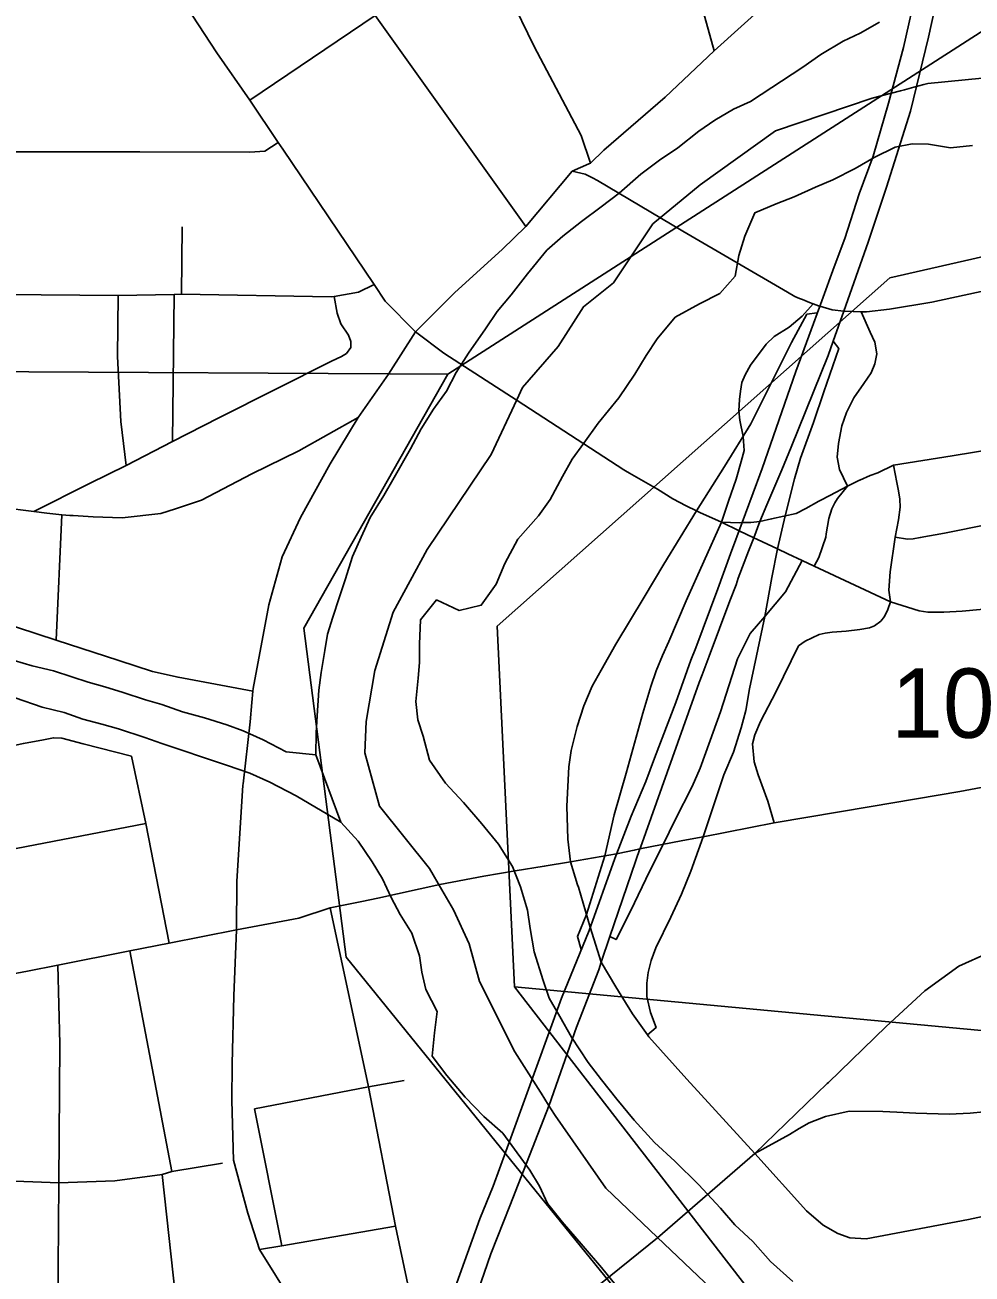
# Model space of a CAD drawing. Extents: x 0 to 34, y 0 to 22.
# Drawn here: x 5.363 to 5.934, y 17.938 to 18.692 of the extents above; entities that cross this region are included whole.
import ezdxf

# ---------------------------------------------------------------- set-up
doc = ezdxf.new("R2010")
doc.units = 0
for name, color, linetype in [('GM_X_City_Street', 7, 'Continuous'), ('GM_X_County_Road', 7, 'Continuous'), ('GM_X_Interchange_Ramps', 7, 'Continuous'), ('GM_X_Interstate_Route', 7, 'Continuous'), ('GM_X_Major_River', 7, 'Continuous'), ('GM_X_Minor_River', 7, 'Continuous'), ('GM_X_Section', 7, 'Continuous'), ('GM_X_Section_Text', 7, 'Continuous'), ('GM_X_State_Route', 7, 'Continuous'), ('GM_X_Township_Road', 7, 'Continuous')]:
    doc.layers.add(name, color=color, linetype=linetype)

msp = doc.modelspace()

# ---------------------------------------------------------------- linework, layer by layer
at = {"layer": 'GM_X_City_Street'}
for p, q in [((5.45717, 18.52964), (5.45757, 18.5704)), ((5.45169, 18.44072), (5.45272, 18.52956)), ((5.38163, 18.32096), (5.38501, 18.39665)), ((5.81473, 18.2106), (5.87317, 18.22049)), ((5.45134, 18.00021), (5.42602, 18.13345)), ((5.84669, 18.05335), (5.80309, 18.01104)), ((5.50112, 18.03802), (5.51773, 17.95544))]:
    msp.add_line(p, q, dxfattribs=at)
for points in [[(5.70382, 18.60876), (5.69817, 18.62546), (5.66986, 18.67924), (5.65476, 18.71038), (5.63867, 18.73899), (5.63778, 18.74057), (5.61042, 18.78398), (5.60565, 18.80325), (5.60403, 18.81271), (5.60004, 18.8227), (5.59103, 18.837), (5.5419, 18.90759), (5.49154, 18.98001), (5.48648, 18.98364), (5.48438, 19.10253), (5.48377, 19.19475), (5.48309, 19.26879), (5.48234, 19.35068), (5.47955, 19.41375), (5.47867, 19.47262), (5.47546, 19.62349)], [(5.41688, 18.92935), (5.466, 18.85737), (5.51512, 18.78539), (5.57404, 18.69794), (5.66478, 18.57054)], [(5.77846, 18.6766), (5.7719, 18.70057), (5.76891, 18.70952), (5.76443, 18.71698), (5.74653, 18.73116), (5.73459, 18.7431), (5.71893, 18.76025), (5.70102, 18.78711), (5.70231, 18.79249)], [(5.70282, 18.60832), (5.70382, 18.60876), (5.71196, 18.6166), (5.74884, 18.64863), (5.77846, 18.6766), (5.81113, 18.70604), (5.83996, 18.73212), (5.85236, 18.74295), (5.85686, 18.75026), (5.86172, 18.76)], [(5.49831, 18.64688), (5.57404, 18.69794), (5.61303, 18.72361), (5.63867, 18.73899)], [(5.01547, 18.61649), (5.06675, 18.61696), (5.11297, 18.61713), (5.18971, 18.61586), (5.20858, 18.61649), (5.2677, 18.61649), (5.27696, 18.61728), (5.34972, 18.61568), (5.43209, 18.61568), (5.49831, 18.61544), (5.50742, 18.616), (5.5155, 18.62119)], [(5.59837, 18.50708), (5.62194, 18.53082), (5.65069, 18.5566), (5.66478, 18.57054), (5.69283, 18.60395), (5.70282, 18.60832)], [(5.82279, 18.53086), (5.75954, 18.5677), (5.70806, 18.59831), (5.70506, 18.6), (5.70072, 18.60212), (5.69283, 18.60395)], [(6.01624, 18.5487), (5.9831, 18.54081), (5.90976, 18.52495), (5.88421, 18.52061), (5.8703, 18.51903), (5.86713, 18.51913), (5.85752, 18.51944), (5.85672, 18.51953), (5.84971, 18.52031), (5.84219, 18.52249), (5.84136, 18.52272), (5.83827, 18.52389), (5.83607, 18.52477), (5.83177, 18.52648)], [(5.06817, 18.52776), (5.11314, 18.52882), (5.18985, 18.52823), (5.20689, 18.5281), (5.26841, 18.52874), (5.34943, 18.52957), (5.41903, 18.529), (5.45272, 18.52956), (5.45717, 18.52964), (5.54743, 18.52805), (5.54926, 18.52837), (5.56395, 18.53091), (5.57328, 18.53553)], [(5.42374, 18.42642), (5.42059, 18.45299), (5.41854, 18.49211), (5.41903, 18.529)], [(5.83177, 18.52648), (5.83005, 18.52717), (5.82712, 18.52833), (5.82279, 18.53086)], [(5.36812, 18.39852), (5.4017, 18.41556), (5.42374, 18.42642), (5.45169, 18.44072), (5.47965, 18.45503), (5.54773, 18.48923), (5.55365, 18.49219), (5.55661, 18.49383), (5.55924, 18.49746), (5.55924, 18.50107), (5.55792, 18.50502), (5.55332, 18.51193), (5.55102, 18.51817), (5.54926, 18.52837)], [(5.83827, 18.52389), (5.83154, 18.51637), (5.82365, 18.50979), (5.8147, 18.50414), (5.80984, 18.49954), (5.80037, 18.48691), (5.79721, 18.48112), (5.79524, 18.47652), (5.79432, 18.47126), (5.79379, 18.46613), (5.7934, 18.45929), (5.79405, 18.45363), (5.79592, 18.44383), (5.79655, 18.43548), (5.79484, 18.42878), (5.79169, 18.41812), (5.78722, 18.40474), (5.78291, 18.39218)], [(5.83886, 18.36564), (5.84155, 18.37078), (5.84575, 18.38309), (5.84611, 18.38516), (5.84767, 18.39435), (5.84947, 18.40009), (5.85013, 18.40145), (5.85126, 18.40377), (5.85288, 18.40642), (5.85899, 18.41392), (5.85417, 18.42401), (5.85265, 18.43127), (5.85357, 18.43969), (5.85554, 18.45034), (5.8583, 18.45837), (5.86277, 18.46718), (5.86882, 18.47573), (5.87316, 18.4823), (5.8754, 18.48769), (5.87658, 18.49374), (5.8754, 18.50072), (5.87264, 18.50677), (5.86713, 18.51913)], [(5.56373, 18.45529), (5.58212, 18.48139), (5.59837, 18.50708)], [(5.59837, 18.50708), (5.61532, 18.49423), (5.65969, 18.46547), (5.72395, 18.42382), (5.72496, 18.4231), (5.7275, 18.42166)], [(5.49961, 18.28333), (5.50018, 18.2901), (5.50032, 18.29175), (5.50983, 18.34234), (5.51786, 18.37131), (5.52884, 18.39502), (5.54679, 18.42735), (5.56373, 18.45529)], [(5.50907, 18.42592), (5.52797, 18.43523), (5.56373, 18.45529)], [(5.9221, 18.43227), (5.94777, 18.43648), (6.03589, 18.45599)], [(5.76987, 18.39794), (5.78291, 18.39218), (5.79373, 18.39182), (5.79529, 18.39184), (5.80053, 18.39192), (5.80606, 18.39246), (5.81309, 18.39405), (5.82791, 18.39741), (5.83383, 18.40037), (5.84172, 18.40481), (5.84235, 18.40514), (5.84833, 18.40831), (5.85899, 18.41392), (5.86621, 18.41747), (5.86637, 18.41753), (5.8726, 18.42026), (5.87721, 18.42184), (5.8867, 18.42646), (5.9221, 18.43227)], [(5.45355, 18.40019), (5.46931, 18.40536), (5.49962, 18.42127), (5.50907, 18.42592)], [(5.8848, 18.34406), (5.88392, 18.35111), (5.88471, 18.36211), (5.88765, 18.383), (5.88968, 18.39358), (5.89076, 18.40128), (5.89056, 18.40611), (5.88978, 18.41104), (5.88869, 18.41617), (5.8867, 18.42646)], [(4.82442, 18.39738), (4.88136, 18.40769), (4.91451, 18.41344), (4.93894, 18.4177), (4.96998, 18.42088), (4.97641, 18.42021), (5.00584, 18.41716), (5.0685, 18.40656), (5.10561, 18.40028), (5.12583, 18.39754), (5.14022, 18.39445), (5.18923, 18.3828), (5.2629, 18.35744), (5.3225, 18.34033), (5.38163, 18.32096), (5.41936, 18.30873), (5.43975, 18.3021), (5.45504, 18.29853), (5.50018, 18.2901)], [(5.7275, 18.42166), (5.74437, 18.4121), (5.75358, 18.40622), (5.76157, 18.40198), (5.76785, 18.39892), (5.76987, 18.39794)], [(5.29075, 18.41333), (5.30709, 18.40994), (5.3326, 18.40449), (5.34896, 18.401), (5.36812, 18.39852), (5.37599, 18.3975), (5.38501, 18.39665), (5.38973, 18.3962), (5.39175, 18.39607)], [(5.88765, 18.383), (5.8951, 18.38185), (5.89846, 18.38204), (5.9028, 18.38283), (5.9174, 18.3855), (6.00035, 18.40226)], [(5.39175, 18.39607), (5.4039, 18.39533), (5.42134, 18.39467), (5.44468, 18.39729), (5.45355, 18.40019)], [(5.78291, 18.39218), (5.7935, 18.38694), (5.80236, 18.38278), (5.80472, 18.38168), (5.81678, 18.37601), (5.82299, 18.37309), (5.83158, 18.36906), (5.83886, 18.36564), (5.8848, 18.34406), (5.90225, 18.33863), (5.90748, 18.33784), (5.91705, 18.33784), (5.928, 18.33843), (5.93905, 18.33952), (6.00716, 18.35064), (6.05364, 18.35922), (6.05869, 18.36005)], [(5.81473, 18.2106), (5.81087, 18.22386), (5.80495, 18.23964), (5.80258, 18.2474), (5.80153, 18.25832), (5.80298, 18.26371), (5.80653, 18.27174), (5.81587, 18.29002), (5.82943, 18.31749), (5.83348, 18.3203), (5.83762, 18.32243), (5.84191, 18.32425), (5.84535, 18.32513), (5.84975, 18.32568), (5.85809, 18.32642), (5.86628, 18.32746), (5.8721, 18.32839), (5.87525, 18.32963), (5.879, 18.33239), (5.88122, 18.3353), (5.88334, 18.33949), (5.8848, 18.34406)], [(5.49432, 18.23432), (5.49862, 18.27171), (5.49961, 18.28333)], [(5.42704, 18.25091), (5.39779, 18.2584), (5.38486, 18.2618), (5.37987, 18.26203), (5.37393, 18.26081), (5.36173, 18.25862), (5.34517, 18.25522), (5.24419, 18.23673), (5.1724, 18.22257), (5.0904, 18.20614), (4.96528, 18.18194), (4.8716, 18.16333), (4.73358, 18.13707), (4.67953, 18.12697), (4.6136, 18.11424), (4.51651, 18.0948)], [(5.44978, 18.13816), (5.43568, 18.21035), (5.42704, 18.25091)], [(5.87317, 18.22049), (5.92659, 18.22953), (5.95671, 18.23524)], [(5.49024, 18.14618), (5.49047, 18.17527), (5.49421, 18.23334), (5.49432, 18.23432)], [(4.39384, 18.00846), (4.46266, 18.02126), (4.54738, 18.03819), (4.62528, 18.05219), (4.74548, 18.07576), (4.88401, 18.10177), (4.97593, 18.12076), (5.10224, 18.14498), (5.20689, 18.16609), (5.23562, 18.17067), (5.34066, 18.19193), (5.35734, 18.19523), (5.43568, 18.21035)], [(5.7596, 18.19993), (5.77186, 18.2023), (5.81473, 18.2106)], [(5.69176, 18.18711), (5.71965, 18.19194), (5.72056, 18.19213), (5.7303, 18.19417), (5.73372, 18.19492), (5.7596, 18.19993)], [(5.73829, 18.08282), (5.74345, 18.08713), (5.74016, 18.0962), (5.73793, 18.10593), (5.73793, 18.11383), (5.73872, 18.1204), (5.74043, 18.12764), (5.74332, 18.13526), (5.7524, 18.15381), (5.75884, 18.16762), (5.7645, 18.18143), (5.77186, 18.2023)], [(5.56603, 18.16328), (5.57563, 18.16525), (5.61292, 18.17344), (5.63955, 18.17847), (5.65849, 18.18163), (5.67601, 18.18446), (5.69176, 18.18711)], [(5.69176, 18.18711), (5.69612, 18.17321), (5.69656, 18.1719), (5.70371, 18.14777), (5.71031, 18.12651), (5.7191, 18.11172), (5.72928, 18.0954), (5.73829, 18.08282)], [(4.89465, 18.02971), (4.98079, 18.04505), (4.99078, 18.04715), (5.11605, 18.07232), (5.19254, 18.08727), (5.22192, 18.09341), (5.2784, 18.10524), (5.30739, 18.11062), (5.35449, 18.11938), (5.36428, 18.1212), (5.38257, 18.12483), (5.42602, 18.13345), (5.44978, 18.13816), (5.49024, 18.14618), (5.52802, 18.15314), (5.54683, 18.15934), (5.56603, 18.16328)], [(5.55264, 17.90513), (5.55693, 17.91155), (5.58192, 17.91441), (5.58763, 17.91584), (5.5935, 17.91919), (5.59588, 17.9245), (5.59366, 17.93207), (5.5862, 17.96725), (5.56986, 18.0514), (5.54683, 18.15934)], [(5.57554, 17.8583), (5.56998, 17.8643), (5.55267, 17.88359), (5.52447, 17.9205), (5.50429, 17.95312), (5.49716, 17.97514), (5.48843, 18.00718), (5.48756, 18.04312), (5.48776, 18.06524), (5.48878, 18.10634), (5.49024, 18.14618)], [(6.04707, 18.15147), (5.98418, 18.1398), (5.94395, 18.13226), (5.92615, 18.12413), (5.90562, 18.10921), (5.8823, 18.0878), (5.84741, 18.05406), (5.84669, 18.05335)], [(5.38183, 17.89137), (5.38249, 17.91743), (5.38313, 17.99352), (5.38377, 18.07727), (5.38257, 18.12483)], [(5.73829, 18.08282), (5.73914, 18.08163), (5.76202, 18.056), (5.80309, 18.01104)], [(5.88865, 18.03609), (5.9002, 18.03556), (5.92031, 18.03494), (5.9329, 18.0354), (5.9576, 18.03796), (5.99225, 18.0439), (6.03938, 18.0538), (6.09365, 18.06509), (6.11781, 18.06905), (6.1515, 18.07558)], [(5.50112, 18.03802), (5.56986, 18.0514), (5.59148, 18.05526)], [(5.82982, 18.02612), (5.83573, 18.02957), (5.84555, 18.03341), (5.85983, 18.03663), (5.88025, 18.03647), (5.88865, 18.03609)], [(5.80309, 18.01104), (5.82391, 18.02266), (5.82982, 18.02612)], [(5.59944, 17.87486), (5.60043, 17.87521), (5.62015, 17.88228), (5.63746, 17.88812), (5.65807, 17.89636), (5.67548, 17.90615), (5.69319, 17.91901), (5.74427, 17.96017), (5.80309, 18.01104)], [(5.80309, 18.01104), (5.83425, 17.97649), (5.8442, 17.96795), (5.85317, 17.96292), (5.86039, 17.9603), (5.87023, 17.95964), (5.93191, 17.97123), (5.96296, 17.97801), (5.98112, 17.98151), (5.99205, 17.98326), (5.99651, 17.98352), (6.01217, 17.98173)], [(5.0827, 17.99808), (5.12811, 18.00599), (5.13496, 18.00623), (5.20891, 17.99592), (5.25768, 17.99681), (5.31459, 17.99596), (5.38313, 17.99352), (5.41695, 17.99468), (5.4454, 17.9985), (5.45134, 18.00021), (5.48193, 18.0053)], [(5.45615, 17.89993), (5.45604, 17.90092), (5.4454, 17.9985)], [(5.50429, 17.95312), (5.51773, 17.95544), (5.5862, 17.96725)]]:
    msp.add_lwpolyline(points, dxfattribs=at)
at = {"layer": 'GM_X_County_Road'}
for points in [[(5.42418, 18.75451), (5.42948, 18.74632), (5.43498, 18.73836), (5.44469, 18.72429), (5.46354, 18.69817), (5.47847, 18.67533), (5.49831, 18.64688), (5.5155, 18.62119), (5.51823, 18.61715)], [(5.51823, 18.61715), (5.57328, 18.53553), (5.58006, 18.52555), (5.59837, 18.50708)]]:
    msp.add_lwpolyline(points, dxfattribs=at)
at = {"layer": 'GM_X_Interchange_Ramps'}
for points in [[(5.84069, 18.51841), (5.83446, 18.51766), (5.82509, 18.50065), (5.80067, 18.45157), (5.78478, 18.42567), (5.76785, 18.39892), (5.74821, 18.36688), (5.73621, 18.34682), (5.71911, 18.31854), (5.71024, 18.30276), (5.70481, 18.29322), (5.69988, 18.28122), (5.69577, 18.26889), (5.69215, 18.25442), (5.69084, 18.24439), (5.68952, 18.22072), (5.69016, 18.20084), (5.69176, 18.18711)], [(5.77186, 18.2023), (5.78431, 18.23957), (5.79007, 18.25334), (5.79479, 18.26793), (5.79767, 18.27841), (5.79973, 18.29157), (5.80906, 18.33522), (5.81329, 18.35877), (5.81678, 18.37601), (5.82138, 18.39593), (5.82685, 18.41836), (5.83055, 18.43069), (5.83836, 18.45227), (5.84457, 18.47081), (5.85369, 18.49695), (5.85036, 18.50145)], [(5.78291, 18.39218), (5.76152, 18.34473), (5.75107, 18.32014), (5.74739, 18.31165), (5.74357, 18.30232), (5.74035, 18.29304), (5.73535, 18.27687), (5.72536, 18.2407), (5.71819, 18.21545), (5.71253, 18.19071), (5.70148, 18.15532), (5.69596, 18.14206), (5.69833, 18.13433)], [(5.71561, 18.142), (5.71936, 18.14027), (5.72819, 18.15774), (5.73945, 18.18124), (5.74762, 18.19761), (5.75497, 18.21254), (5.76523, 18.23266), (5.77009, 18.24371), (5.77338, 18.25318), (5.78226, 18.27767), (5.79262, 18.30957), (5.80018, 18.32502), (5.80906, 18.33522), (5.82151, 18.35014), (5.83158, 18.36906)]]:
    msp.add_lwpolyline(points, dxfattribs=at)
at = {"layer": 'GM_X_Interstate_Route'}
for points in [[(5.81035, 18.40259), (5.81932, 18.42378), (5.82484, 18.43739), (5.84732, 18.4928), (5.85036, 18.50145), (5.85672, 18.51953), (5.87138, 18.56119), (5.88237, 18.5943), (5.89696, 18.64013), (5.90785, 18.68493), (5.9169, 18.72624), (5.91848, 18.73186), (5.92445, 18.75934), (5.92808, 18.77407)], [(5.62035, 17.92519), (5.6371, 17.97161), (5.64513, 17.9914), (5.6567, 18.0227), (5.68629, 18.10477), (5.70298, 18.14574), (5.71853, 18.18907), (5.72845, 18.21464), (5.73729, 18.23556), (5.74239, 18.24979), (5.75535, 18.28332), (5.76433, 18.30887), (5.76741, 18.31632), (5.7807, 18.35183), (5.78842, 18.373), (5.79529, 18.39184), (5.80399, 18.4152), (5.80463, 18.41693), (5.80741, 18.42448), (5.82769, 18.48315), (5.84341, 18.5258), (5.85093, 18.54619), (5.85734, 18.56339), (5.86589, 18.59035), (5.87431, 18.61297), (5.88365, 18.64493), (5.89272, 18.6786), (5.90086, 18.71543)], [(5.79926, 18.37466), (5.80236, 18.38278), (5.80606, 18.39246), (5.81035, 18.40259)], [(5.77125, 18.29998), (5.77546, 18.31126), (5.78802, 18.3447), (5.79166, 18.35439), (5.79305, 18.35842), (5.79926, 18.37466)], [(5.73406, 18.19586), (5.76618, 18.28637), (5.7695, 18.29528), (5.77125, 18.29998)], [(5.69723, 18.09203), (5.70897, 18.12196), (5.71031, 18.12651), (5.71561, 18.142), (5.73372, 18.19492), (5.73406, 18.19586)], [(5.65515, 17.97947), (5.67901, 18.04021), (5.6954, 18.08736), (5.69723, 18.09203)], [(5.56137, 17.67415), (5.56597, 17.69937), (5.57189, 17.7281), (5.5822, 17.77219), (5.59229, 17.8075), (5.60032, 17.82973), (5.6105, 17.85729), (5.62015, 17.88228), (5.64377, 17.95051), (5.65515, 17.97947)]]:
    msp.add_lwpolyline(points, dxfattribs=at)
at = {"layer": 'GM_X_Major_River'}
msp.add_line((5.53816, 18.25172), (5.55331, 18.21114), dxfattribs=at)
for points in [[(5.87813, 18.69385), (5.8666, 18.68725), (5.85625, 18.68252), (5.84279, 18.67443), (5.832, 18.66668), (5.80045, 18.64605), (5.7901, 18.64132), (5.77895, 18.63471), (5.76932, 18.62807), (5.75659, 18.61807), (5.74543, 18.6107), (5.73424, 18.60219), (5.7211, 18.59068), (5.7103, 18.58254), (5.69835, 18.57367), (5.68716, 18.56478), (5.6775, 18.55624), (5.66582, 18.54204), (5.65607, 18.52932), (5.64751, 18.51924), (5.64047, 18.50874), (5.63031, 18.49413), (5.62286, 18.48251), (5.61694, 18.47123), (5.60913, 18.46037), (5.60167, 18.44837), (5.59536, 18.43634), (5.58552, 18.41906), (5.57923, 18.40817), (5.57099, 18.39504), (5.56544, 18.383), (5.56027, 18.37133), (5.55581, 18.35736), (5.55218, 18.34642), (5.54853, 18.33471), (5.54529, 18.32452), (5.54357, 18.31468), (5.54142, 18.30143), (5.54007, 18.29082), (5.539, 18.27526), (5.53842, 18.26502), (5.53816, 18.25172)], [(5.65687, 18.18434), (5.6484, 18.19781), (5.63839, 18.21017), (5.62724, 18.22293), (5.61645, 18.23455), (5.60685, 18.24842), (5.60296, 18.26294), (5.59973, 18.27288), (5.59843, 18.28393), (5.59985, 18.29796), (5.60079, 18.30743), (5.60063, 18.31846), (5.6013, 18.33326), (5.61103, 18.34522), (5.62459, 18.33886), (5.63794, 18.34201), (5.64693, 18.35474), (5.65211, 18.36717), (5.66, 18.38183), (5.67244, 18.39601), (5.67947, 18.40575), (5.68696, 18.41965), (5.69286, 18.43017), (5.69989, 18.4399), (5.70849, 18.45189), (5.72095, 18.46721), (5.73072, 18.48145), (5.7374, 18.49271), (5.74406, 18.50283), (5.75496, 18.5159), (5.76955, 18.52396), (5.78183, 18.53017), (5.79115, 18.54062), (5.7933, 18.55311), (5.79695, 18.56482), (5.80292, 18.57875), (5.81594, 18.58418), (5.82667, 18.58852), (5.8397, 18.59433), (5.85004, 18.59868), (5.86347, 18.60562), (5.875, 18.61223), (5.88766, 18.61843), (5.89795, 18.6205), (5.90783, 18.62029), (5.92108, 18.61812), (5.9344, 18.61937)], [(5.55331, 18.21114), (5.56372, 18.19953), (5.57221, 18.1872), (5.57847, 18.17682), (5.58357, 18.1657), (5.58906, 18.15532), (5.59606, 18.14417), (5.60072, 18.13039), (5.60205, 18.12049), (5.60451, 18.11018), (5.61146, 18.09674), (5.60968, 18.08386), (5.60827, 18.06983), (5.61716, 18.05825), (5.6283, 18.04511), (5.63946, 18.03348), (5.65104, 18.02337), (5.65807, 18.01373), (5.66732, 18.001), (5.6732, 17.99138), (5.67794, 17.98103), (5.68683, 17.96983), (5.69946, 17.95514), (5.7106, 17.94237), (5.72173, 17.92847)], [(5.82592, 17.93393), (5.81248, 17.94599), (5.80171, 17.95798), (5.79089, 17.96808), (5.78235, 17.97814), (5.76895, 17.99247), (5.75479, 18.00643), (5.74248, 18.0177), (5.73021, 18.03125), (5.71982, 18.044), (5.71056, 18.05559), (5.7024, 18.06601), (5.69245, 18.08141), (5.68547, 18.09371), (5.67886, 18.10486), (5.67527, 18.11558), (5.66991, 18.13278), (5.66753, 18.14689), (5.66585, 18.15794), (5.66157, 18.17208), (5.65687, 18.18434)]]:
    msp.add_lwpolyline(points, dxfattribs=at)
at = {"layer": 'GM_X_Minor_River'}
msp.add_line((5.55331, 18.21114), (5.53816, 18.25172), dxfattribs=at)
for points in [[(5.53816, 18.25172), (5.52034, 18.25361), (5.50642, 18.26073), (5.49438, 18.26629), (5.48457, 18.26991), (5.47098, 18.27399), (5.45775, 18.27767), (5.44531, 18.28211), (5.43548, 18.28497), (5.4219, 18.28942), (5.41094, 18.29268), (5.40074, 18.29555), (5.39093, 18.29879), (5.37999, 18.30243), (5.36713, 18.30535), (5.35618, 18.30862)], [(5.35687, 18.28619), (5.3731, 18.28054), (5.38633, 18.27723), (5.39764, 18.2732), (5.40899, 18.27031), (5.41918, 18.26744), (5.43504, 18.26218), (5.44522, 18.25855), (5.4573, 18.25451), (5.47051, 18.25006), (5.48485, 18.24521), (5.49843, 18.24075), (5.51048, 18.23519), (5.52627, 18.22689), (5.55331, 18.21114)]]:
    msp.add_lwpolyline(points, dxfattribs=at)
at = {"layer": 'GM_X_Section'}
for points in [[(5.98962, 19.50419), (6.02559, 19.44292), (6.02539, 18.74343), (5.61791, 18.48139), (5.03965, 18.48463), (5.03707, 19.50155)], [(5.65796, 18.11177), (5.64764, 18.32935), (5.88448, 18.53966), (6.16441, 18.60335), (6.11806, 18.06871)], [(5.03965, 18.48463), (5.61791, 18.48139), (5.53096, 18.32812), (5.55642, 18.12958), (5.94095, 17.65517), (5.94104, 17.65505), (5.94524, 17.63735), (5.96217, 17.59121), (6.02854, 17.45475), (6.02664, 17.37374), (5.04609, 17.39252)], [(5.65796, 18.11177), (6.11806, 18.06871), (6.07317, 17.51262), (6.01213, 17.65383)]]:
    msp.add_lwpolyline(points, close=True, dxfattribs=at)
at = {"layer": 'GM_X_State_Route'}
for points in [[(5.81035, 18.40259), (5.81932, 18.42378), (5.82484, 18.43739), (5.84732, 18.4928), (5.85036, 18.50145), (5.85672, 18.51953), (5.87138, 18.56119), (5.88237, 18.5943), (5.89696, 18.64013), (5.90785, 18.68493), (5.9169, 18.72624), (5.91848, 18.73186), (5.92445, 18.75934), (5.92808, 18.77407)], [(5.79926, 18.37466), (5.80236, 18.38278), (5.80606, 18.39246), (5.81035, 18.40259)], [(5.77125, 18.29998), (5.77546, 18.31126), (5.78802, 18.3447), (5.79166, 18.35439), (5.79305, 18.35842), (5.79926, 18.37466)], [(5.73406, 18.19586), (5.76618, 18.28637), (5.7695, 18.29528), (5.77125, 18.29998)], [(5.69723, 18.09203), (5.70897, 18.12196), (5.71031, 18.12651), (5.71561, 18.142), (5.73372, 18.19492), (5.73406, 18.19586)], [(5.65515, 17.97947), (5.67901, 18.04021), (5.6954, 18.08736), (5.69723, 18.09203)], [(5.56137, 17.67415), (5.56597, 17.69937), (5.57189, 17.7281), (5.5822, 17.77219), (5.59229, 17.8075), (5.60032, 17.82973), (5.6105, 17.85729), (5.62015, 17.88228), (5.64377, 17.95051), (5.65515, 17.97947)]]:
    msp.add_lwpolyline(points, dxfattribs=at)
at = {"layer": 'GM_X_Township_Road'}
for points in [[(5.80142, 17.90613), (5.74404, 17.9607), (5.71307, 17.99016), (5.68263, 18.03412), (5.68219, 18.03475), (5.6786, 18.04039), (5.67402, 18.04758), (5.67366, 18.04814), (5.65817, 18.07247), (5.6369, 18.11502), (5.63073, 18.13764), (5.62129, 18.15822), (5.6142, 18.1703), (5.60671, 18.18308), (5.57669, 18.2208), (5.56768, 18.25296), (5.56854, 18.27182), (5.57368, 18.30269), (5.58483, 18.33784), (5.60541, 18.37557), (5.64401, 18.43301), (5.65946, 18.46601), (5.66288, 18.47331), (5.68432, 18.49818), (5.69975, 18.52218), (5.71779, 18.53659), (5.74158, 18.57227), (5.7701, 18.59575), (5.81556, 18.62833), (5.87389, 18.64804), (5.8908, 18.6525), (5.89327, 18.65315), (5.89895, 18.65465), (5.90503, 18.65625), (5.90743, 18.65688), (6.01798, 18.66775)], [(6.01798, 18.66775), (5.90743, 18.65688), (5.90503, 18.65625), (5.89895, 18.65465), (5.89327, 18.65315), (5.8908, 18.6525), (5.87389, 18.64804), (5.81556, 18.62833), (5.7701, 18.59575), (5.74158, 18.57227), (5.71779, 18.53659), (5.69975, 18.52218), (5.68432, 18.49818), (5.66288, 18.47331), (5.65946, 18.46601), (5.64401, 18.43301), (5.60541, 18.37557), (5.58483, 18.33784), (5.57368, 18.30269), (5.56854, 18.27182), (5.56768, 18.25296), (5.57669, 18.2208), (5.60671, 18.18308), (5.6142, 18.1703), (5.62129, 18.15822), (5.63073, 18.13764), (5.6369, 18.11502), (5.65817, 18.07247), (5.67366, 18.04814), (5.67402, 18.04758), (5.6786, 18.04039), (5.68219, 18.03475), (5.68263, 18.03412), (5.71307, 17.99016), (5.74404, 17.9607), (5.80142, 17.90613)]]:
    msp.add_lwpolyline(points, dxfattribs=at)

# ---------------------------------------------------------------- texts
at = {"layer": 'GM_X_Section_Text'}
msp.add_text('10', height=0.041856, rotation=0.00001, dxfattribs=at).set_placement((5.88535, 18.26199))

doc.saveas('drawing.dxf')
